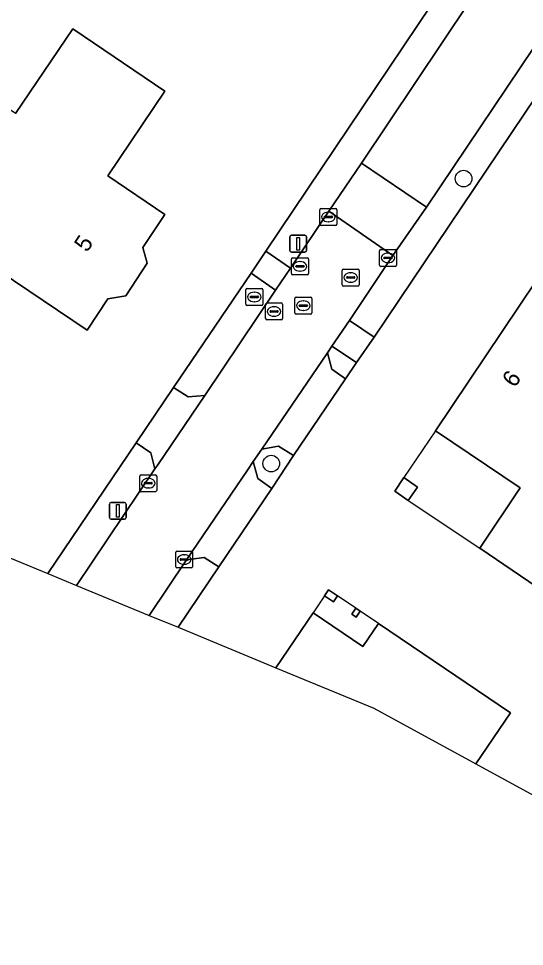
# Model space of a CAD drawing. Extents: x 163859 to 164644, y 379566 to 382155.
# Drawn here: x 164144.9 to 164174.8, y 381764.7 to 381819.5 of the extents above; entities that cross this region are included whole.
import ezdxf

# ---------------------------------------------------------------- set-up
doc = ezdxf.new("R2010")
doc.units = 0
for name, color, linetype in [('IMGEO_Boom', 7, 'Continuous'), ('IMGEO_Brandkraan', 7, 'Continuous'), ('IMGEO_Erf', 7, 'Continuous'), ('IMGEO_Groenvoorziening', 7, 'Continuous'), ('IMGEO_Kolk', 7, 'Continuous'), ('IMGEO_Lichtmast', 7, 'Continuous'), ('IMGEO_Pand', 7, 'Continuous'), ('IMGEO_Pand_nummerreeks', 7, 'Continuous'), ('IMGEO_Pand_overbouw', 7, 'Continuous'), ('IMGEO_Rijbaan_lokaal_open', 7, 'Continuous'), ('IMGEO_Rioolput', 7, 'Continuous'), ('IMGEO_Voetpad_halfverhard', 7, 'Continuous'), ('IMGEO_Voetpad_open', 7, 'Continuous')]:
    doc.layers.add(name, color=color, linetype=linetype)

msp = doc.modelspace()

# ---------------------------------------------------------------- linework, layer by layer
at = {"layer": 'IMGEO_Boom'}
for centre in [(164171.182, 381810.055), (164159.808, 381793.206)]:
    msp.add_circle(centre, 0.489, dxfattribs=at)
at = {"layer": 'IMGEO_Brandkraan'}
for p, q in [((164158.385, 381803.554), (164159.237, 381803.554)), ((164158.31, 381802.628), (164158.31, 381803.48)), ((164158.569, 381803.048), (164158.569, 381803.06)), ((164159.007, 381803.011), (164158.609, 381803.011)), ((164158.612, 381803.097), (164159.01, 381803.097)), ((164158.798, 381803.334), (164158.823, 381803.334)), ((164159.053, 381803.06), (164159.053, 381803.048)), ((164159.311, 381803.48), (164159.311, 381802.628)), ((164159.237, 381802.554), (164158.385, 381802.554)), ((164158.821, 381802.774), (164158.796, 381802.774))]:
    msp.add_line(p, q, dxfattribs=at)
for points in [[(164158.385, 381803.554), (164159.237, 381803.554)], [(164158.31, 381802.628), (164158.31, 381803.48)], [(164159.311, 381803.48), (164159.311, 381802.628)], [(164159.237, 381802.554), (164158.385, 381802.554)]]:
    msp.add_lwpolyline(points, dxfattribs=at)
for centre, radius, start, end in [((164158.387, 381803.478), 0.0765, 91.552, 178.448), ((164158.387, 381803.478), 0.0765, 91.552, 178.448), ((164159.235, 381803.478), 0.0765, 1.552, 88.448), ((164159.235, 381803.478), 0.0765, 1.552, 88.448), ((164158.609, 381803.057), 0.0403, 85.8775, 175.7526), ((164158.606, 381803.047), 0.0366, 178.938, 274.7102), ((164159.01, 381803.054), 0.043, 264.8664, 352.4533), ((164159.014, 381803.059), 0.0386, 1.7309, 96.639), ((164158.387, 381802.63), 0.0765, 181.552, 268.448), ((164158.387, 381802.63), 0.0765, 181.552, 268.448), ((164159.235, 381802.63), 0.0765, 271.552, 358.448), ((164159.235, 381802.63), 0.0765, 271.552, 358.448)]:
    msp.add_arc(centre, radius, start, end, dxfattribs=at)
for centre, major_axis, ratio, start_param, end_param in [((164158.797, 381803.054), (-0.387, 0.002), 0.722429, 4.712389, 7.853982), ((164158.822, 381803.054), (-0.39, 0.002), 0.717154, 1.570796, 4.712389)]:
    msp.add_ellipse(centre, major_axis=major_axis, ratio=ratio, start_param=start_param, end_param=end_param, dxfattribs=at)
at = {"layer": 'IMGEO_Erf'}
for points in [[(164185.088, 381829.228), (164165.885, 381800.687), (164164.857, 381799.186), (164164.201, 381798.208), (164161.124, 381793.688), (164159.838, 381791.733), (164156.707, 381787.104), (164154.295, 381783.529)], [(164140.833, 381789.08), (164146.594, 381786.705), (164151.818, 381794.439), (164154.029, 381797.699), (164158.614, 381804.471), (164159.489, 381805.76), (164170.069, 381821.522)], [(164144.68, 381813.904), (164148.072, 381818.907), (164153.52, 381815.225), (164150.139, 381810.208), (164153.512, 381807.933), (164152.206, 381805.986), (164152.475, 381805.058), (164151.199, 381803.13), (164150.146, 381802.936), (164148.912, 381801.099), (164139.349, 381807.527)], [(164154.295, 381783.529), (164160.086, 381781.142), (164162.28, 381784.386), (164165.229, 381782.391), (164166.15, 381783.749), (164173.951, 381778.472), (164171.914, 381775.46), (164191.699, 381764.664)]]:
    msp.add_lwpolyline(points, dxfattribs=at)
for points in [[(164172.134, 381788.209), (164174.528, 381791.769), (164169.519, 381795.147), (164175.479, 381804.003), (164188.769, 381795.078), (164180.351, 381782.639)], [(164167.116, 381791.569), (164167.65, 381792.375), (164168.456, 381791.821), (164167.909, 381791.024)], [(164162.954, 381785.391), (164163.193, 381785.749), (164163.722, 381785.395), (164163.482, 381785.038)], [(164164.565, 381784.304), (164164.809, 381784.658), (164165.064, 381784.482), (164164.821, 381784.128)]]:
    msp.add_lwpolyline(points, close=True, dxfattribs=at)
at = {"layer": 'IMGEO_Groenvoorziening'}
msp.add_lwpolyline([(164159.256, 381794.06), (164158.744, 381793.325), (164159.007, 381792.319), (164159.838, 381791.733), (164161.124, 381793.688), (164160.233, 381794.231)], close=True, dxfattribs=at)
at = {"layer": 'IMGEO_Kolk'}
for p, q in [((164162.687, 381807.358), (164162.687, 381808.21)), ((164162.762, 381808.284), (164163.614, 381808.284)), ((164163.175, 381808.064), (164163.2, 381808.064)), ((164163.688, 381808.21), (164163.688, 381807.358)), ((164162.946, 381807.778), (164162.946, 381807.79)), ((164163.384, 381807.741), (164162.986, 381807.741)), ((164162.989, 381807.827), (164163.387, 381807.827)), ((164163.198, 381807.504), (164163.173, 381807.504)), ((164163.43, 381807.79), (164163.43, 381807.778)), ((164163.614, 381807.284), (164162.762, 381807.284)), ((164166.206, 381804.939), (164166.206, 381805.791)), ((164166.281, 381805.865), (164167.133, 381805.865)), ((164167.207, 381805.791), (164167.207, 381804.939)), ((164166.465, 381805.359), (164166.465, 381805.371)), ((164166.903, 381805.322), (164166.505, 381805.322)), ((164166.508, 381805.408), (164166.906, 381805.408)), ((164166.694, 381805.645), (164166.719, 381805.645)), ((164166.949, 381805.371), (164166.949, 381805.359)), ((164167.133, 381804.865), (164166.281, 381804.865)), ((164166.717, 381805.085), (164166.692, 381805.085)), ((164152.031, 381791.62), (164152.031, 381792.472)), ((164152.106, 381792.546), (164152.958, 381792.546)), ((164152.29, 381792.04), (164152.29, 381792.052)), ((164152.333, 381792.089), (164152.731, 381792.089)), ((164152.519, 381792.326), (164152.544, 381792.326)), ((164152.774, 381792.052), (164152.774, 381792.04)), ((164153.032, 381792.472), (164153.032, 381791.62)), ((164152.958, 381791.546), (164152.106, 381791.546)), ((164152.728, 381792.003), (164152.33, 381792.003)), ((164152.542, 381791.766), (164152.517, 381791.766)), ((164154.157, 381787.109), (164154.157, 381787.961)), ((164154.232, 381788.035), (164155.084, 381788.035)), ((164154.645, 381787.815), (164154.67, 381787.815)), ((164155.158, 381787.961), (164155.158, 381787.109)), ((164154.416, 381787.529), (164154.416, 381787.541)), ((164154.854, 381787.492), (164154.456, 381787.492)), ((164154.459, 381787.578), (164154.857, 381787.578)), ((164154.668, 381787.255), (164154.643, 381787.255)), ((164154.9, 381787.541), (164154.9, 381787.529)), ((164155.084, 381787.035), (164154.232, 381787.035))]:
    msp.add_line(p, q, dxfattribs=at)
for points in [[(164162.687, 381807.358), (164162.687, 381808.21)], [(164162.762, 381808.284), (164163.614, 381808.284)], [(164163.688, 381808.21), (164163.688, 381807.358)], [(164163.614, 381807.284), (164162.762, 381807.284)], [(164166.206, 381804.939), (164166.206, 381805.791)], [(164166.281, 381805.865), (164167.133, 381805.865)], [(164167.207, 381805.791), (164167.207, 381804.939)], [(164167.133, 381804.865), (164166.281, 381804.865)], [(164152.031, 381791.62), (164152.031, 381792.472)], [(164152.106, 381792.546), (164152.958, 381792.546)], [(164153.032, 381792.472), (164153.032, 381791.62)], [(164152.958, 381791.546), (164152.106, 381791.546)], [(164154.157, 381787.109), (164154.157, 381787.961)], [(164154.232, 381788.035), (164155.084, 381788.035)], [(164155.158, 381787.961), (164155.158, 381787.109)], [(164155.084, 381787.035), (164154.232, 381787.035)]]:
    msp.add_lwpolyline(points, dxfattribs=at)
for centre, radius, start, end in [((164162.764, 381808.208), 0.0765, 91.552, 178.448), ((164162.764, 381808.208), 0.0765, 91.552, 178.448), ((164163.612, 381808.208), 0.0765, 1.552, 88.448), ((164163.612, 381808.208), 0.0765, 1.552, 88.448), ((164162.986, 381807.787), 0.0403, 85.8775, 175.7526), ((164162.983, 381807.777), 0.0366, 178.938, 274.7102), ((164163.387, 381807.784), 0.043, 264.8664, 352.4533), ((164163.391, 381807.789), 0.0386, 1.7309, 96.639), ((164162.764, 381807.36), 0.0765, 181.552, 268.448), ((164162.764, 381807.36), 0.0765, 181.552, 268.448), ((164163.612, 381807.36), 0.0765, 271.552, 358.448), ((164163.612, 381807.36), 0.0765, 271.552, 358.448), ((164166.283, 381805.789), 0.0765, 91.552, 178.448), ((164166.283, 381805.789), 0.0765, 91.552, 178.448), ((164167.131, 381805.789), 0.0765, 1.552, 88.448), ((164167.131, 381805.789), 0.0765, 1.552, 88.448), ((164166.505, 381805.368), 0.0403, 85.8775, 175.7526), ((164166.502, 381805.358), 0.0366, 178.938, 274.7102), ((164166.906, 381805.365), 0.043, 264.8664, 352.4533), ((164166.91, 381805.37), 0.0386, 1.7309, 96.639), ((164166.283, 381804.941), 0.0765, 181.552, 268.448), ((164166.283, 381804.941), 0.0765, 181.552, 268.448), ((164167.131, 381804.941), 0.0765, 271.552, 358.448), ((164167.131, 381804.941), 0.0765, 271.552, 358.448), ((164152.108, 381792.47), 0.0765, 91.552, 178.448), ((164152.108, 381792.47), 0.0765, 91.552, 178.448), ((164152.33, 381792.049), 0.0403, 85.8775, 175.7526), ((164152.327, 381792.039), 0.0366, 178.938, 274.7102), ((164152.731, 381792.046), 0.043, 264.8664, 352.4533), ((164152.735, 381792.051), 0.0386, 1.7309, 96.639), ((164152.956, 381792.47), 0.0765, 1.552, 88.448), ((164152.956, 381792.47), 0.0765, 1.552, 88.448), ((164152.108, 381791.622), 0.0765, 181.552, 268.448), ((164152.108, 381791.622), 0.0765, 181.552, 268.448), ((164152.956, 381791.622), 0.0765, 271.552, 358.448), ((164152.956, 381791.622), 0.0765, 271.552, 358.448), ((164154.234, 381787.959), 0.0765, 91.552, 178.448), ((164154.234, 381787.959), 0.0765, 91.552, 178.448), ((164155.082, 381787.959), 0.0765, 1.552, 88.448), ((164155.082, 381787.959), 0.0765, 1.552, 88.448), ((164154.234, 381787.111), 0.0765, 181.552, 268.448), ((164154.234, 381787.111), 0.0765, 181.552, 268.448), ((164154.456, 381787.538), 0.0403, 85.8775, 175.7526), ((164154.453, 381787.528), 0.0366, 178.938, 274.7102), ((164154.857, 381787.535), 0.043, 264.8664, 352.4533), ((164154.861, 381787.54), 0.0386, 1.7309, 96.639), ((164155.082, 381787.111), 0.0765, 271.552, 358.448), ((164155.082, 381787.111), 0.0765, 271.552, 358.448)]:
    msp.add_arc(centre, radius, start, end, dxfattribs=at)
for centre, major_axis, ratio, start_param, end_param in [((164163.174, 381807.784), (-0.387, 0.002), 0.722429, 4.712389, 7.853982), ((164163.199, 381807.784), (-0.39, 0.002), 0.717154, 1.570796, 4.712389), ((164166.693, 381805.365), (-0.387, 0.002), 0.722429, 4.712389, 7.853982), ((164166.718, 381805.365), (-0.39, 0.002), 0.717154, 1.570796, 4.712389), ((164152.518, 381792.046), (-0.387, 0.002), 0.722429, 4.712389, 7.853982), ((164152.543, 381792.046), (-0.39, 0.002), 0.717154, 1.570796, 4.712389), ((164154.644, 381787.535), (-0.387, 0.002), 0.722429, 4.712389, 7.853982), ((164154.669, 381787.535), (-0.39, 0.002), 0.717154, 1.570796, 4.712389)]:
    msp.add_ellipse(centre, major_axis=major_axis, ratio=ratio, start_param=start_param, end_param=end_param, dxfattribs=at)
at = {"layer": 'IMGEO_Lichtmast'}
for p, q in [((164160.905, 381805.805), (164160.905, 381806.605)), ((164160.905, 381806.605), (164160.905, 381805.805)), ((164161.005, 381806.705), (164161.795, 381806.705)), ((164161.795, 381806.705), (164161.005, 381806.705)), ((164161.895, 381806.605), (164161.895, 381805.805)), ((164161.895, 381805.805), (164161.895, 381806.605)), ((164161.795, 381805.705), (164161.005, 381805.705)), ((164161.005, 381805.705), (164161.795, 381805.705)), ((164150.235, 381790.015), (164150.235, 381790.815)), ((164150.235, 381790.815), (164150.235, 381790.015)), ((164150.335, 381790.915), (164151.125, 381790.915)), ((164151.125, 381790.915), (164150.335, 381790.915)), ((164151.225, 381790.815), (164151.225, 381790.015)), ((164151.225, 381790.015), (164151.225, 381790.815)), ((164151.125, 381789.915), (164150.335, 381789.915)), ((164150.335, 381789.915), (164151.125, 381789.915))]:
    msp.add_line(p, q, dxfattribs=at)
for points in [[(164161.325, 381806.58), (164161.475, 381806.58), (164161.475, 381805.83), (164161.325, 381805.83), (164161.325, 381806.58)], [(164150.655, 381790.79), (164150.805, 381790.79), (164150.805, 381790.04), (164150.655, 381790.04), (164150.655, 381790.79)]]:
    msp.add_lwpolyline(points, dxfattribs=at)
for centre, start, end in [((164161.005, 381806.605), 90, 180), ((164161.005, 381806.605), 90, 180), ((164161.795, 381806.605), 0, 90), ((164161.795, 381806.605), 360, 90), ((164161.005, 381805.805), 180, 270), ((164161.005, 381805.805), 180, 270), ((164161.795, 381805.805), 270, 0), ((164161.795, 381805.805), 270, 0), ((164150.335, 381790.815), 90, 180), ((164150.335, 381790.815), 90, 180), ((164151.125, 381790.815), 0, 90), ((164151.125, 381790.815), 360, 90), ((164150.335, 381790.015), 180, 270), ((164150.335, 381790.015), 180, 270), ((164151.125, 381790.015), 270, 0), ((164151.125, 381790.015), 270, 0)]:
    msp.add_arc(centre, 0.1, start, end, dxfattribs=at)
at = {"layer": 'IMGEO_Pand'}
for points in [[(164150.139, 381810.208), (164153.52, 381815.225), (164148.072, 381818.907), (164144.68, 381813.904), (164139.628, 381817.322), (164135.123, 381810.665), (164135.139, 381810.654), (164135.339, 381810.521), (164138.626, 381808.297), (164138.494, 381808.102), (164139.349, 381807.527), (164148.912, 381801.099), (164150.146, 381802.936), (164151.199, 381803.13), (164152.475, 381805.058), (164152.206, 381805.986), (164153.512, 381807.933)], [(164188.769, 381795.078), (164175.479, 381804.003), (164169.519, 381795.147), (164174.528, 381791.769), (164172.134, 381788.209), (164180.351, 381782.639)], [(164168.456, 381791.821), (164167.65, 381792.375), (164167.116, 381791.569), (164167.909, 381791.024)], [(164163.722, 381785.395), (164163.193, 381785.749), (164162.954, 381785.391), (164163.482, 381785.038)], [(164171.914, 381775.46), (164173.951, 381778.472), (164166.15, 381783.749), (164165.229, 381782.391), (164162.28, 381784.386), (164160.086, 381781.142), (164165.877, 381778.754)], [(164165.064, 381784.482), (164164.809, 381784.658), (164164.565, 381784.304), (164164.821, 381784.128)]]:
    msp.add_lwpolyline(points, close=True, dxfattribs=at)
at = {"layer": 'IMGEO_Pand_overbouw'}
for points in [[(164167.909, 381791.024), (164172.134, 381788.209), (164174.528, 381791.769), (164169.519, 381795.147), (164167.65, 381792.375), (164167.116, 381791.569)], [(164165.229, 381782.391), (164166.15, 381783.749), (164165.064, 381784.482), (164164.809, 381784.658), (164163.722, 381785.395), (164163.193, 381785.749), (164162.954, 381785.391), (164162.28, 381784.386)]]:
    msp.add_lwpolyline(points, close=True, dxfattribs=at)
at = {"layer": 'IMGEO_Rijbaan_lokaal_open'}
for points in [[(164194.609, 381854.612), (164194.104, 381853.864), (164192.817, 381851.959), (164186.204, 381842.193), (164185.505, 381841.141), (164183.67, 381838.426), (164181.218, 381834.798), (164177.875, 381829.852), (164174.051, 381824.163), (164172.275, 381821.514), (164171.541, 381820.495), (164165.146, 381810.963), (164168.994, 381808.366), (164183.294, 381829.671)], [(164148.287, 381786.006), (164152.597, 381784.229), (164154.795, 381787.522), (164156.465, 381789.976), (164158.404, 381792.826), (164158.744, 381793.325), (164159.256, 381794.06), (164163.13, 381799.747), (164163.391, 381800.153), (164164.432, 381801.664), (164167.007, 381805.504), (164163.204, 381808.122), (164160.947, 381804.756), (164160.068, 381803.456), (164155.87, 381797.223), (164153.097, 381793.141), (164152.932, 381792.897), (164148.287, 381786.006)]]:
    msp.add_lwpolyline(points, dxfattribs=at)
for points in [[(164165.146, 381810.963), (164163.204, 381808.122), (164167.007, 381805.504), (164168.994, 381808.366)], [(164164.201, 381798.208), (164163.386, 381798.783), (164163.13, 381799.747), (164159.256, 381794.06), (164160.233, 381794.231), (164161.124, 381793.688)], [(164155.87, 381797.223), (164154.884, 381797.145), (164154.029, 381797.699), (164151.818, 381794.439), (164152.678, 381793.841), (164152.932, 381792.897), (164153.097, 381793.141)], [(164159.838, 381791.733), (164159.007, 381792.319), (164158.744, 381793.325), (164158.404, 381792.826), (164156.465, 381789.976), (164154.795, 381787.522), (164155.842, 381787.656), (164156.707, 381787.104)]]:
    msp.add_lwpolyline(points, close=True, dxfattribs=at)
at = {"layer": 'IMGEO_Rioolput'}
for p, q in [((164161.009, 381804.438), (164161.009, 381805.29)), ((164161.084, 381805.364), (164161.936, 381805.364)), ((164162.01, 381805.29), (164162.01, 381804.438)), ((164161.268, 381804.858), (164161.268, 381804.87)), ((164161.706, 381804.821), (164161.308, 381804.821)), ((164161.311, 381804.907), (164161.709, 381804.907)), ((164161.497, 381805.144), (164161.522, 381805.144)), ((164161.752, 381804.87), (164161.752, 381804.858)), ((164164.005, 381803.778), (164164.005, 381804.63)), ((164164.08, 381804.704), (164164.932, 381804.704)), ((164165.006, 381804.63), (164165.006, 381803.778)), ((164161.936, 381804.364), (164161.084, 381804.364)), ((164161.52, 381804.584), (164161.495, 381804.584)), ((164164.264, 381804.198), (164164.264, 381804.21)), ((164164.702, 381804.161), (164164.304, 381804.161)), ((164164.307, 381804.247), (164164.705, 381804.247)), ((164164.493, 381804.484), (164164.518, 381804.484)), ((164164.748, 381804.21), (164164.748, 381804.198)), ((164164.932, 381803.704), (164164.08, 381803.704)), ((164164.516, 381803.924), (164164.491, 381803.924)), ((164161.28, 381803.043), (164162.132, 381803.043)), ((164159.474, 381801.774), (164159.474, 381802.626)), ((164159.549, 381802.7), (164160.401, 381802.7)), ((164159.962, 381802.48), (164159.987, 381802.48)), ((164160.475, 381802.626), (164160.475, 381801.774)), ((164161.205, 381802.117), (164161.205, 381802.969)), ((164161.464, 381802.537), (164161.464, 381802.549)), ((164161.902, 381802.5), (164161.504, 381802.5)), ((164161.507, 381802.586), (164161.905, 381802.586)), ((164161.693, 381802.823), (164161.718, 381802.823)), ((164161.948, 381802.549), (164161.948, 381802.537)), ((164162.206, 381802.969), (164162.206, 381802.117)), ((164159.733, 381802.194), (164159.733, 381802.206)), ((164160.171, 381802.157), (164159.773, 381802.157)), ((164159.776, 381802.243), (164160.174, 381802.243)), ((164159.985, 381801.92), (164159.96, 381801.92)), ((164160.217, 381802.206), (164160.217, 381802.194)), ((164162.132, 381802.043), (164161.28, 381802.043)), ((164161.716, 381802.263), (164161.691, 381802.263)), ((164160.401, 381801.7), (164159.549, 381801.7))]:
    msp.add_line(p, q, dxfattribs=at)
for points in [[(164161.009, 381804.438), (164161.009, 381805.29)], [(164161.084, 381805.364), (164161.936, 381805.364)], [(164162.01, 381805.29), (164162.01, 381804.438)], [(164164.005, 381803.778), (164164.005, 381804.63)], [(164164.08, 381804.704), (164164.932, 381804.704)], [(164165.006, 381804.63), (164165.006, 381803.778)], [(164161.936, 381804.364), (164161.084, 381804.364)], [(164164.932, 381803.704), (164164.08, 381803.704)], [(164161.28, 381803.043), (164162.132, 381803.043)], [(164159.474, 381801.774), (164159.474, 381802.626)], [(164159.549, 381802.7), (164160.401, 381802.7)], [(164160.475, 381802.626), (164160.475, 381801.774)], [(164161.205, 381802.117), (164161.205, 381802.969)], [(164162.206, 381802.969), (164162.206, 381802.117)], [(164162.132, 381802.043), (164161.28, 381802.043)], [(164160.401, 381801.7), (164159.549, 381801.7)]]:
    msp.add_lwpolyline(points, dxfattribs=at)
for centre, radius, start, end in [((164161.086, 381805.288), 0.0765, 91.552, 178.448), ((164161.086, 381805.288), 0.0765, 91.552, 178.448), ((164161.934, 381805.288), 0.0765, 1.552, 88.448), ((164161.934, 381805.288), 0.0765, 1.552, 88.448), ((164161.308, 381804.867), 0.0403, 85.8775, 175.7526), ((164161.305, 381804.857), 0.0366, 178.938, 274.7102), ((164161.709, 381804.864), 0.043, 264.8664, 352.4533), ((164161.713, 381804.869), 0.0386, 1.7309, 96.639), ((164164.082, 381804.628), 0.0765, 91.552, 178.448), ((164164.082, 381804.628), 0.0765, 91.552, 178.448), ((164164.93, 381804.628), 0.0765, 1.552, 88.448), ((164164.93, 381804.628), 0.0765, 1.552, 88.448), ((164161.086, 381804.44), 0.0765, 181.552, 268.448), ((164161.086, 381804.44), 0.0765, 181.552, 268.448), ((164161.934, 381804.44), 0.0765, 271.552, 358.448), ((164161.934, 381804.44), 0.0765, 271.552, 358.448), ((164164.304, 381804.207), 0.0403, 85.8775, 175.7526), ((164164.301, 381804.197), 0.0366, 178.938, 274.7102), ((164164.705, 381804.204), 0.043, 264.8664, 352.4533), ((164164.709, 381804.209), 0.0386, 1.7309, 96.639), ((164164.082, 381803.78), 0.0765, 181.552, 268.448), ((164164.082, 381803.78), 0.0765, 181.552, 268.448), ((164164.93, 381803.78), 0.0765, 271.552, 358.448), ((164164.93, 381803.78), 0.0765, 271.552, 358.448), ((164161.282, 381802.967), 0.0765, 91.552, 178.448), ((164161.282, 381802.967), 0.0765, 91.552, 178.448), ((164162.13, 381802.967), 0.0765, 1.552, 88.448), ((164162.13, 381802.967), 0.0765, 1.552, 88.448), ((164159.551, 381802.624), 0.0765, 91.552, 178.448), ((164159.551, 381802.624), 0.0765, 91.552, 178.448), ((164160.399, 381802.624), 0.0765, 1.552, 88.448), ((164160.399, 381802.624), 0.0765, 1.552, 88.448), ((164161.504, 381802.546), 0.0403, 85.8775, 175.7526), ((164161.501, 381802.536), 0.0366, 178.938, 274.7102), ((164161.905, 381802.543), 0.043, 264.8664, 352.4533), ((164161.909, 381802.548), 0.0386, 1.7309, 96.639), ((164159.773, 381802.203), 0.0403, 85.8775, 175.7526), ((164159.77, 381802.193), 0.0366, 178.938, 274.7102), ((164160.174, 381802.2), 0.043, 264.8664, 352.4533), ((164160.178, 381802.205), 0.0386, 1.7309, 96.639), ((164161.282, 381802.119), 0.0765, 181.552, 268.448), ((164161.282, 381802.119), 0.0765, 181.552, 268.448), ((164162.13, 381802.119), 0.0765, 271.552, 358.448), ((164162.13, 381802.119), 0.0765, 271.552, 358.448), ((164159.551, 381801.776), 0.0765, 181.552, 268.448), ((164159.551, 381801.776), 0.0765, 181.552, 268.448), ((164160.399, 381801.776), 0.0765, 271.552, 358.448), ((164160.399, 381801.776), 0.0765, 271.552, 358.448)]:
    msp.add_arc(centre, radius, start, end, dxfattribs=at)
for centre, major_axis, ratio, start_param, end_param in [((164161.496, 381804.864), (-0.387, 0.002), 0.722429, 4.712389, 7.853982), ((164161.521, 381804.864), (-0.39, 0.002), 0.717154, 1.570796, 4.712389), ((164164.492, 381804.204), (-0.387, 0.002), 0.722429, 4.712389, 7.853982), ((164164.517, 381804.204), (-0.39, 0.002), 0.717154, 1.570796, 4.712389), ((164159.961, 381802.2), (-0.387, 0.002), 0.722429, 4.712389, 7.853982), ((164159.986, 381802.2), (-0.39, 0.002), 0.717154, 1.570796, 4.712389), ((164161.692, 381802.543), (-0.387, 0.002), 0.722429, 4.712389, 7.853982), ((164161.717, 381802.543), (-0.39, 0.002), 0.717154, 1.570796, 4.712389)]:
    msp.add_ellipse(centre, major_axis=major_axis, ratio=ratio, start_param=start_param, end_param=end_param, dxfattribs=at)
at = {"layer": 'IMGEO_Voetpad_halfverhard'}
for points in [[(164185.088, 381829.228), (164184.248, 381829.772), (164183.294, 381829.671), (164168.994, 381808.366), (164167.007, 381805.504), (164164.432, 381801.664), (164165.885, 381800.687)], [(164171.541, 381820.495), (164170.069, 381821.522), (164159.489, 381805.76), (164160.947, 381804.756), (164163.204, 381808.122), (164165.146, 381810.963)], [(164160.068, 381803.456), (164158.614, 381804.471), (164154.029, 381797.699), (164154.884, 381797.145), (164155.87, 381797.223)], [(164163.391, 381800.153), (164163.13, 381799.747), (164163.386, 381798.783), (164164.201, 381798.208), (164164.857, 381799.186)], [(164148.287, 381786.006), (164152.932, 381792.897), (164152.678, 381793.841), (164151.818, 381794.439), (164146.594, 381786.705)], [(164154.295, 381783.529), (164156.707, 381787.104), (164155.842, 381787.656), (164154.795, 381787.522), (164152.597, 381784.229)]]:
    msp.add_lwpolyline(points, close=True, dxfattribs=at)
at = {"layer": 'IMGEO_Voetpad_open'}
for points in [[(164160.947, 381804.756), (164159.489, 381805.76), (164158.614, 381804.471), (164160.068, 381803.456)], [(164165.885, 381800.687), (164164.432, 381801.664), (164163.391, 381800.153), (164164.857, 381799.186)]]:
    msp.add_lwpolyline(points, close=True, dxfattribs=at)

# ---------------------------------------------------------------- texts
at = {"layer": 'IMGEO_Pand_nummerreeks'}
for s, rotation, p in [('5', 56.4249, (164148.916, 381805.65)), ('6', 55.8634, (164174.214, 381797.648))]:
    msp.add_text(s, height=1, rotation=rotation, dxfattribs=at).set_placement(p)

doc.saveas('drawing.dxf')
